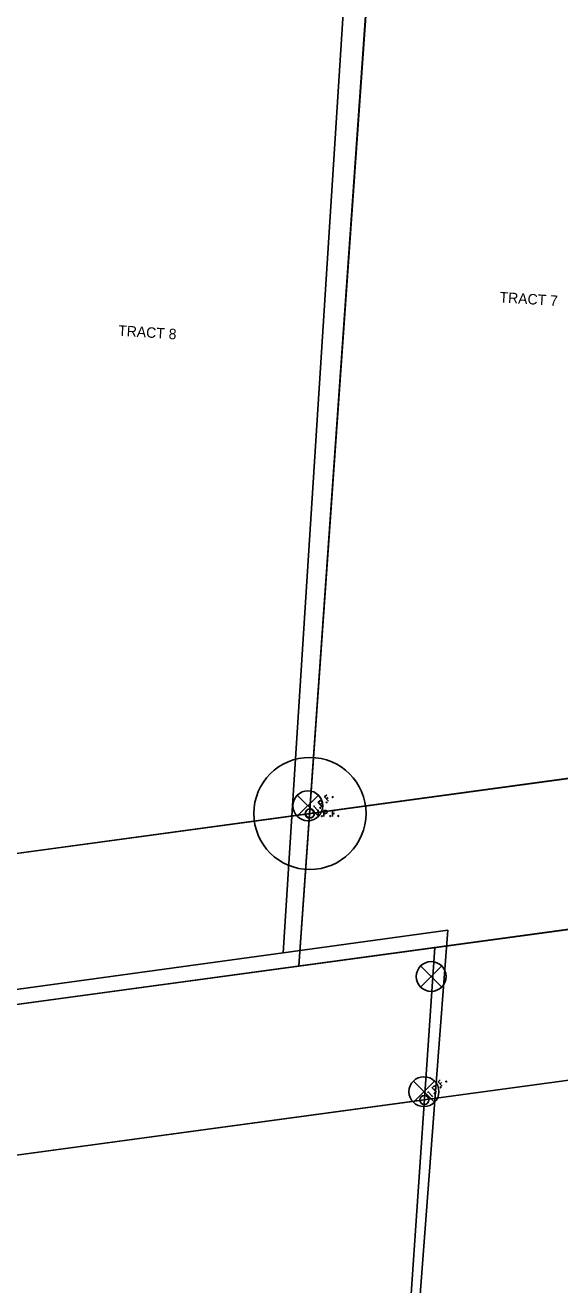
# Model space of a CAD drawing. Extents: x 1532954 to 1577849, y 698998 to 706606.
# Drawn here: x 1574063.3 to 1574206.2, y 703101.1 to 703438.2 of the extents above; entities that cross this region are included whole.
import ezdxf

# ---------------------------------------------------------------- set-up
doc = ezdxf.new("R2010")
doc.units = 0
for name, color, linetype in [('Default', 7, 'Continuous'), ('DV_X_Property_Line', 7, 'Continuous'), ('RW_X_Esmt_SH', 7, 'Continuous'), ('SC_Scratch1', 7, 'Continuous'), ('SC_Scratch10', 7, 'Continuous'), ('SC_Scratch3', 7, 'Continuous'), ('SC_Scratch4', 7, 'Continuous'), ('SC_Scratch9', 7, 'Continuous'), ('SV_X_Mon_Cells_Found', 7, 'Continuous')]:
    doc.layers.add(name, color=color, linetype=linetype)

msp = doc.modelspace()

# ---------------------------------------------------------------- linework, layer by layer
at = {"layer": 'Default'}
for p, q in [((1574136.03, 703232.15), (1574141.69, 703226.49)), ((1574136.03, 703226.49), (1574141.69, 703232.15)), ((1574138.86, 703229.32), (1574138.86, 703229.32)), ((1574168.99, 703186.46), (1574174.64, 703180.81)), ((1574168.99, 703180.81), (1574174.64, 703186.46)), ((1574171.82, 703183.63), (1574171.82, 703183.63)), ((1574167.07, 703155.65), (1574172.72, 703149.99)), ((1574167.07, 703149.99), (1574172.72, 703155.65)), ((1574169.89, 703152.82), (1574169.89, 703152.82))]:
    msp.add_line(p, q, dxfattribs=at)
for centre in [(1574138.86, 703229.32), (1574171.82, 703183.63), (1574169.89, 703152.82)]:
    msp.add_circle(centre, 4, dxfattribs=at)
at = {"layer": 'DV_X_Property_Line'}
for p, q in [((1574136.48, 703186.47), (1574188.16, 703924.56)), ((1574152.51, 702894.98), (1574172.79, 703191.41))]:
    msp.add_line(p, q, dxfattribs=at)
at = {"layer": 'RW_X_Esmt_SH'}
for p, q in [((1574050.43, 703215.11), (1574859.76, 703325.41)), ((1571959, 702849.32), (1574870.56, 703246.15))]:
    msp.add_line(p, q, dxfattribs=at)
at = {"layer": 'SC_Scratch1'}
msp.add_lwpolyline([(1574623.21, 704615.75), (1574580.13, 703940.99), (1574479.08, 703927.65), (1574283.38, 703901.81), (1574176.78, 703887.73), (1574134.84, 703230.69), (1574132.24, 703189.96), (1574047.81, 703178.38), (1574037.25, 703176.93), (1574039.84, 703217.66), (1574053.75, 703435.89), (1574059.56, 703527.11), (1574066.62, 703637.88), (1574073.68, 703748.66), (1574080.74, 703859.43), (1574081.75, 703875.18), (1574087.8, 703970.21), (1574094.86, 704080.98), (1574101.92, 704191.76)], dxfattribs=at)
msp.add_lwpolyline([(1574173.16, 703155.19), (1574157.49, 702947.32), (1574153.57, 702895.41), (1573992.57, 702907.55), (1573992.57, 702907.55), (1574009.55, 703132.76), (1574012.63, 703173.56), (1574037.25, 703176.93), (1574047.81, 703178.38), (1574132.24, 703189.96), (1574176.24, 703195.99)], close=True, dxfattribs=at)
at = {"layer": 'SC_Scratch10'}
for p, q in [((1571190.11, 702825.26), (1574958.12, 703338.82)), ((1571190.11, 702825.26), (1574958.12, 703338.82)), ((1571190.11, 702825.26), (1574958.12, 703338.82)), ((1571195.51, 702785.63), (1574963.52, 703299.19)), ((1571200.91, 702745.99), (1574968.92, 703259.55))]:
    msp.add_line(p, q, dxfattribs=at)
at = {"layer": 'SC_Scratch3'}
for p, q in [((1574136.47, 703186.42), (1574188.53, 703925.45)), ((1574832.97, 703321.42), (1574040.25, 703213.72)), ((1574830.1, 703280.66), (1574037.38, 703172.96)), ((1574533, 703240.3), (1572963.42, 703027.05)), ((1574532.5, 703240.23), (1574172.81, 703191.36)), ((1574172.81, 703191.36), (1574045.04, 703174))]:
    msp.add_line(p, q, dxfattribs=at)
for points in [[(1574143.9, 703232.24), (1574143.33, 703231.74), (1574144.38, 703230.54)], [(1574143.84, 703231.15), (1574144.25, 703231.51)], [(1574145.4, 703231.72), (1574145.44, 703231.75), (1574145.49, 703231.75), (1574145.54, 703231.74), (1574145.59, 703231.69), (1574145.59, 703231.63), (1574145.59, 703231.59), (1574145.54, 703231.55), (1574145.5, 703231.55), (1574145.44, 703231.57), (1574145.4, 703231.62), (1574145.39, 703231.67), (1574145.4, 703231.72)], [(1574140.33, 703229.11), (1574140.59, 703229.34)], [(1574141.52, 703228.02), (1574140.46, 703229.23)], [(1574141.38, 703227.91), (1574141.65, 703228.14)], [(1574142.69, 703229.06), (1574141.64, 703230.26), (1574142.04, 703230.61), (1574142.09, 703230.63), (1574142.16, 703230.67), (1574142.2, 703230.67), (1574142.24, 703230.67), (1574142.32, 703230.65), (1574142.38, 703230.63), (1574142.47, 703230.57), (1574142.57, 703230.45), (1574142.59, 703230.41), (1574142.63, 703230.34), (1574142.65, 703230.24), (1574142.64, 703230.18), (1574142.63, 703230.14), (1574142.61, 703230.09), (1574142.55, 703230.02), (1574142.15, 703229.67)], [(1574142.1, 703228.82), (1574142.14, 703228.85), (1574142.18, 703228.86), (1574142.24, 703228.84), (1574142.28, 703228.79), (1574142.29, 703228.73), (1574142.28, 703228.69), (1574142.24, 703228.66), (1574142.2, 703228.65), (1574142.14, 703228.67), (1574142.1, 703228.72), (1574142.09, 703228.78), (1574142.1, 703228.82)], [(1574143.79, 703230.3), (1574143.83, 703230.34), (1574143.87, 703230.34), (1574143.93, 703230.32), (1574143.97, 703230.27), (1574143.98, 703230.21), (1574143.97, 703230.17), (1574143.93, 703230.14), (1574143.89, 703230.13), (1574143.83, 703230.15), (1574143.79, 703230.2), (1574143.78, 703230.26), (1574143.79, 703230.3)]]:
    msp.add_lwpolyline(points, dxfattribs=at)
msp.add_circle((1574139.34, 703227.18), 1.2, dxfattribs=at)
at = {"layer": 'SC_Scratch4'}
for p, q in [((1574045.04, 703174.01), (1574172.81, 703191.37)), ((1574172.81, 703191.37), (1574156.5, 702954.02)), ((1574042.24, 703133.26), (1574170.01, 703150.62))]:
    msp.add_line(p, q, dxfattribs=at)
for points in [[(1574173.22, 703152.72), (1574172.08, 703153.85), (1574172.46, 703154.22), (1574172.5, 703154.25), (1574172.58, 703154.29), (1574172.62, 703154.3), (1574172.66, 703154.3), (1574172.73, 703154.29), (1574172.8, 703154.27), (1574172.89, 703154.21), (1574173, 703154.11), (1574173.03, 703154.06), (1574173.06, 703153.99), (1574173.1, 703153.9), (1574173.09, 703153.84), (1574173.09, 703153.8), (1574173.06, 703153.75), (1574173.01, 703153.67), (1574172.64, 703153.3)], [(1574174.2, 703155.98), (1574173.67, 703155.44), (1574174.8, 703154.32)], [(1574174.22, 703154.89), (1574174.6, 703155.28)], [(1574174.22, 703154.04), (1574174.26, 703154.08), (1574174.3, 703154.08), (1574174.36, 703154.07), (1574174.41, 703154.03), (1574174.42, 703153.97), (1574174.42, 703153.93), (1574174.38, 703153.89), (1574174.34, 703153.88), (1574174.28, 703153.89), (1574174.23, 703153.94), (1574174.22, 703154), (1574174.22, 703154.04)], [(1574175.74, 703155.56), (1574175.78, 703155.6), (1574175.82, 703155.61), (1574175.88, 703155.6), (1574175.92, 703155.55), (1574175.93, 703155.49), (1574175.93, 703155.45), (1574175.89, 703155.41), (1574175.85, 703155.41), (1574175.79, 703155.42), (1574175.75, 703155.46), (1574175.73, 703155.52), (1574175.74, 703155.56)], [(1574170.86, 703152.61), (1574171.11, 703152.86)], [(1574172.12, 703151.61), (1574170.98, 703152.74)], [(1574171.99, 703151.48), (1574172.24, 703151.74)], [(1574172.64, 703152.44), (1574172.68, 703152.48), (1574172.72, 703152.49), (1574172.78, 703152.47), (1574172.83, 703152.43), (1574172.84, 703152.37), (1574172.83, 703152.33), (1574172.79, 703152.29), (1574172.75, 703152.29), (1574172.69, 703152.3), (1574172.65, 703152.34), (1574172.64, 703152.4), (1574172.64, 703152.44)]]:
    msp.add_lwpolyline(points, dxfattribs=at)
msp.add_circle((1574170.01, 703150.62), 1.2, dxfattribs=at)
at = {"layer": 'SC_Scratch9'}
msp.add_circle((1574139.41, 703227.26), 15, dxfattribs=at)
at = {"layer": 'SV_X_Mon_Cells_Found'}
for points in [[(1574141.42, 703228.06), (1574141.78, 703228.06)], [(1574141.6, 703226.46), (1574141.6, 703228.06)], [(1574143.17, 703226.46), (1574143.17, 703228.06), (1574143.69, 703228.06), (1574143.75, 703228.05), (1574143.83, 703228.02), (1574143.86, 703228), (1574143.89, 703227.97), (1574143.94, 703227.91), (1574143.97, 703227.84), (1574143.99, 703227.74), (1574143.99, 703227.59), (1574143.98, 703227.54), (1574143.96, 703227.47), (1574143.92, 703227.38), (1574143.87, 703227.34), (1574143.84, 703227.32), (1574143.78, 703227.29), (1574143.69, 703227.28), (1574143.17, 703227.28)], [(1574146.18, 703228.06), (1574145.41, 703228.06), (1574145.41, 703226.46)], [(1574141.42, 703226.46), (1574141.78, 703226.46)], [(1574142.56, 703226.67), (1574142.61, 703226.67), (1574142.65, 703226.65), (1574142.68, 703226.6), (1574142.68, 703226.53), (1574142.65, 703226.48), (1574142.61, 703226.46), (1574142.56, 703226.46), (1574142.53, 703226.48), (1574142.49, 703226.53), (1574142.49, 703226.6), (1574142.53, 703226.65), (1574142.56, 703226.67)], [(1574144.81, 703226.67), (1574144.86, 703226.67), (1574144.9, 703226.65), (1574144.93, 703226.6), (1574144.93, 703226.53), (1574144.9, 703226.48), (1574144.86, 703226.46), (1574144.81, 703226.46), (1574144.78, 703226.48), (1574144.74, 703226.53), (1574144.74, 703226.6), (1574144.78, 703226.65), (1574144.81, 703226.67)], [(1574145.41, 703227.28), (1574145.95, 703227.28)], [(1574146.96, 703226.67), (1574147.01, 703226.67), (1574147.05, 703226.65), (1574147.08, 703226.6), (1574147.08, 703226.53), (1574147.05, 703226.48), (1574147.01, 703226.46), (1574146.96, 703226.46), (1574146.92, 703226.48), (1574146.89, 703226.53), (1574146.89, 703226.6), (1574146.92, 703226.65), (1574146.96, 703226.67)]]:
    msp.add_lwpolyline(points, dxfattribs=at)
msp.add_circle((1574139.41, 703227.26), 1.2, dxfattribs=at)

# ---------------------------------------------------------------- texts
at = {"layer": 'SC_Scratch3'}
for s, p in [('TRACT 7', (1574190.03, 703364.03)), ('TRACT 8', (1574088.08, 703355.11))]:
    msp.add_text(s, height=2.8, rotation=356.2372, dxfattribs=at).set_placement(p)

doc.saveas('drawing.dxf')
